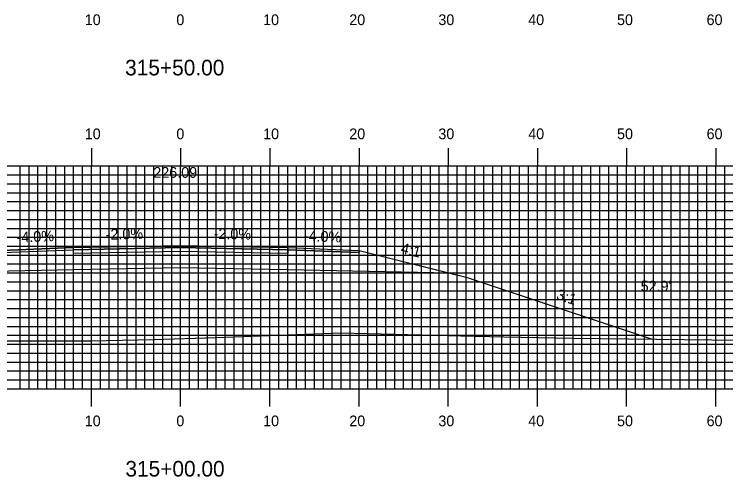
# Model space of a CAD drawing. Extents: x 1819244 to 1819587, y 442591 to 442811.
# Drawn here: x 1819391 to 1819470.8, y 442643.8 to 442695.7 of the extents above; entities that cross this region are included whole.
import ezdxf

# ---------------------------------------------------------------- set-up
doc = ezdxf.new("R2010")
doc.units = 0
for name, color, linetype in [('ANNOTATION', 7, 'Continuous'), ('D_Roadway_Centerline', 7, 'Continuous'), ('D_Roadway_Centerline_Text', 7, 'Continuous'), ('D_Roadway_Edge_Shoulder', 7, 'Continuous'), ('D_Roadway_Edge_TW', 7, 'Continuous'), ('D_Roadway_Pavement', 7, 'Continuous'), ('D_Roadway_SlopeLines', 7, 'Continuous'), ('D_Roadway_SubGrade', 7, 'Continuous'), ('D_Text_Standard', 7, 'Continuous'), ('H_V ANNOTATION', 7, 'Continuous'), ('MAJOR', 7, 'Continuous'), ('MINOR', 7, 'Continuous'), ('S_Roadway_Centerline', 7, 'Continuous')]:
    doc.layers.add(name, color=color, linetype=linetype)

msp = doc.modelspace()

# ---------------------------------------------------------------- linework, layer by layer
at = {"layer": 'D_Roadway_Centerline'}
msp.add_lwpolyline([(1819356.354, 442659.088), (1819377.665, 442666.192), (1819379.491, 442666.648), (1819389.665, 442669.192), (1819397.665, 442669.512), (1819409.665, 442669.752), (1819421.665, 442669.512), (1819429.665, 442669.192), (1819439.839, 442666.648), (1819441.665, 442666.192), (1819462.524, 442659.238)], dxfattribs=at)
at = {"layer": 'D_Roadway_Edge_Shoulder'}
for points in [[(1819397.665, 442669.512), (1819389.665, 442669.192), (1819389.665, 442668.942), (1819397.665, 442669.262)], [(1819421.665, 442669.512), (1819429.665, 442669.192), (1819429.665, 442668.942), (1819421.665, 442669.262)]]:
    msp.add_lwpolyline(points, close=True, dxfattribs=at)
at = {"layer": 'D_Roadway_Edge_TW'}
msp.add_lwpolyline([(1819397.665, 442669.262), (1819397.665, 442669.512), (1819409.665, 442669.752), (1819421.665, 442669.512), (1819421.665, 442669.262), (1819409.665, 442669.502)], close=True, dxfattribs=at)
at = {"layer": 'D_Roadway_Pavement'}
msp.add_lwpolyline([(1819397.665, 442668.845), (1819397.665, 442669.262), (1819409.665, 442669.502), (1819421.665, 442669.262), (1819421.665, 442668.845), (1819409.665, 442669.085)], close=True, dxfattribs=at)
at = {"layer": 'D_Roadway_SlopeLines'}
msp.add_lwpolyline([(1819429.665, 442669.192), (1819441.665, 442666.192), (1819462.524, 442659.238)], dxfattribs=at)
at = {"layer": 'D_Roadway_SubGrade'}
msp.add_lwpolyline([(1819397.665, 442667.012), (1819379.491, 442666.648), (1819389.665, 442669.192), (1819389.665, 442668.942), (1819397.665, 442669.262), (1819409.665, 442669.502), (1819421.665, 442669.262), (1819429.665, 442668.942), (1819429.665, 442669.192), (1819439.839, 442666.648), (1819421.665, 442667.012), (1819409.665, 442667.252)], close=True, dxfattribs=at)
at = {"layer": 'MAJOR'}
for p, q in [((1819399.665, 442680.669), (1819399.665, 442678.665)), ((1819409.665, 442680.669), (1819409.665, 442678.665)), ((1819419.665, 442680.669), (1819419.665, 442678.665)), ((1819429.665, 442680.669), (1819429.665, 442678.665)), ((1819439.665, 442680.669), (1819439.665, 442678.665)), ((1819449.665, 442680.669), (1819449.665, 442678.665)), ((1819459.665, 442680.669), (1819459.665, 442678.665)), ((1819469.665, 442680.669), (1819469.665, 442678.665)), ((1819269.665, 442678.665), (1819549.665, 442678.665)), ((1819269.665, 442678.665), (1819549.665, 442678.665)), ((1819399.665, 442653.665), (1819399.665, 442678.665)), ((1819409.665, 442653.665), (1819409.665, 442678.665)), ((1819419.665, 442653.665), (1819419.665, 442678.665)), ((1819429.665, 442653.665), (1819429.665, 442678.665)), ((1819439.665, 442653.665), (1819439.665, 442678.665)), ((1819449.665, 442653.665), (1819449.665, 442678.665)), ((1819459.665, 442653.665), (1819459.665, 442678.665)), ((1819469.665, 442653.665), (1819469.665, 442678.665)), ((1819269.665, 442673.665), (1819549.665, 442673.665)), ((1819269.665, 442668.665), (1819549.665, 442668.665)), ((1819269.665, 442663.665), (1819549.665, 442663.665)), ((1819269.665, 442658.665), (1819549.665, 442658.665)), ((1819269.665, 442653.665), (1819549.665, 442653.665)), ((1819269.665, 442653.665), (1819549.665, 442653.665)), ((1819399.665, 442651.661), (1819399.665, 442653.665)), ((1819409.665, 442651.661), (1819409.665, 442653.665)), ((1819419.665, 442651.661), (1819419.665, 442653.665)), ((1819429.665, 442651.661), (1819429.665, 442653.665)), ((1819439.665, 442651.661), (1819439.665, 442653.665)), ((1819449.665, 442651.661), (1819449.665, 442653.665)), ((1819459.665, 442651.661), (1819459.665, 442653.665)), ((1819469.665, 442651.661), (1819469.665, 442653.665))]:
    msp.add_line(p, q, dxfattribs=at)
at = {"layer": 'MINOR'}
for p, q in [((1819391.665, 442653.665), (1819391.665, 442678.665)), ((1819392.665, 442653.665), (1819392.665, 442678.665)), ((1819393.665, 442653.665), (1819393.665, 442678.665)), ((1819394.665, 442653.665), (1819394.665, 442678.665)), ((1819395.665, 442653.665), (1819395.665, 442678.665)), ((1819396.665, 442653.665), (1819396.665, 442678.665)), ((1819397.665, 442653.665), (1819397.665, 442678.665)), ((1819398.665, 442653.665), (1819398.665, 442678.665)), ((1819400.665, 442653.665), (1819400.665, 442678.665)), ((1819401.665, 442653.665), (1819401.665, 442678.665)), ((1819402.665, 442653.665), (1819402.665, 442678.665)), ((1819403.665, 442653.665), (1819403.665, 442678.665)), ((1819404.665, 442653.665), (1819404.665, 442678.665)), ((1819405.665, 442653.665), (1819405.665, 442678.665)), ((1819406.665, 442653.665), (1819406.665, 442678.665)), ((1819407.665, 442653.665), (1819407.665, 442678.665)), ((1819408.665, 442653.665), (1819408.665, 442678.665)), ((1819410.665, 442653.665), (1819410.665, 442678.665)), ((1819411.665, 442653.665), (1819411.665, 442678.665)), ((1819412.665, 442653.665), (1819412.665, 442678.665)), ((1819413.665, 442653.665), (1819413.665, 442678.665)), ((1819414.665, 442653.665), (1819414.665, 442678.665)), ((1819415.665, 442653.665), (1819415.665, 442678.665)), ((1819416.665, 442653.665), (1819416.665, 442678.665)), ((1819417.665, 442653.665), (1819417.665, 442678.665)), ((1819418.665, 442653.665), (1819418.665, 442678.665)), ((1819420.665, 442653.665), (1819420.665, 442678.665)), ((1819421.665, 442653.665), (1819421.665, 442678.665)), ((1819422.665, 442653.665), (1819422.665, 442678.665)), ((1819423.665, 442653.665), (1819423.665, 442678.665)), ((1819424.665, 442653.665), (1819424.665, 442678.665)), ((1819425.665, 442653.665), (1819425.665, 442678.665)), ((1819426.665, 442653.665), (1819426.665, 442678.665)), ((1819427.665, 442653.665), (1819427.665, 442678.665)), ((1819428.665, 442653.665), (1819428.665, 442678.665)), ((1819430.665, 442653.665), (1819430.665, 442678.665)), ((1819431.665, 442653.665), (1819431.665, 442678.665)), ((1819432.665, 442653.665), (1819432.665, 442678.665)), ((1819433.665, 442653.665), (1819433.665, 442678.665)), ((1819434.665, 442653.665), (1819434.665, 442678.665)), ((1819435.665, 442653.665), (1819435.665, 442678.665)), ((1819436.665, 442653.665), (1819436.665, 442678.665)), ((1819437.665, 442653.665), (1819437.665, 442678.665)), ((1819438.665, 442653.665), (1819438.665, 442678.665)), ((1819440.665, 442653.665), (1819440.665, 442678.665)), ((1819441.665, 442653.665), (1819441.665, 442678.665)), ((1819442.665, 442653.665), (1819442.665, 442678.665)), ((1819443.665, 442653.665), (1819443.665, 442678.665)), ((1819444.665, 442653.665), (1819444.665, 442678.665)), ((1819445.665, 442653.665), (1819445.665, 442678.665)), ((1819446.665, 442653.665), (1819446.665, 442678.665)), ((1819447.665, 442653.665), (1819447.665, 442678.665)), ((1819448.665, 442653.665), (1819448.665, 442678.665)), ((1819450.665, 442653.665), (1819450.665, 442678.665)), ((1819451.665, 442653.665), (1819451.665, 442678.665)), ((1819452.665, 442653.665), (1819452.665, 442678.665)), ((1819453.665, 442653.665), (1819453.665, 442678.665)), ((1819454.665, 442653.665), (1819454.665, 442678.665)), ((1819455.665, 442653.665), (1819455.665, 442678.665)), ((1819456.665, 442653.665), (1819456.665, 442678.665)), ((1819457.665, 442653.665), (1819457.665, 442678.665)), ((1819458.665, 442653.665), (1819458.665, 442678.665)), ((1819460.665, 442653.665), (1819460.665, 442678.665)), ((1819461.665, 442653.665), (1819461.665, 442678.665)), ((1819462.665, 442653.665), (1819462.665, 442678.665)), ((1819463.665, 442653.665), (1819463.665, 442678.665)), ((1819464.665, 442653.665), (1819464.665, 442678.665)), ((1819465.665, 442653.665), (1819465.665, 442678.665)), ((1819466.665, 442653.665), (1819466.665, 442678.665)), ((1819467.665, 442653.665), (1819467.665, 442678.665)), ((1819468.665, 442653.665), (1819468.665, 442678.665)), ((1819470.665, 442653.665), (1819470.665, 442678.665)), ((1819269.665, 442677.665), (1819549.665, 442677.665)), ((1819269.665, 442676.665), (1819549.665, 442676.665)), ((1819269.665, 442675.665), (1819549.665, 442675.665)), ((1819269.665, 442674.665), (1819549.665, 442674.665)), ((1819269.665, 442672.665), (1819549.665, 442672.665)), ((1819269.665, 442671.665), (1819549.665, 442671.665)), ((1819269.665, 442670.665), (1819549.665, 442670.665)), ((1819269.665, 442669.665), (1819549.665, 442669.665)), ((1819269.665, 442667.665), (1819549.665, 442667.665)), ((1819269.665, 442666.665), (1819549.665, 442666.665)), ((1819269.665, 442665.665), (1819549.665, 442665.665)), ((1819269.665, 442664.665), (1819549.665, 442664.665)), ((1819269.665, 442662.665), (1819549.665, 442662.665)), ((1819269.665, 442661.665), (1819549.665, 442661.665)), ((1819269.665, 442660.665), (1819549.665, 442660.665)), ((1819269.665, 442659.665), (1819549.665, 442659.665)), ((1819269.665, 442657.665), (1819549.665, 442657.665)), ((1819269.665, 442656.665), (1819549.665, 442656.665)), ((1819269.665, 442655.665), (1819549.665, 442655.665)), ((1819269.665, 442654.665), (1819549.665, 442654.665))]:
    msp.add_line(p, q, dxfattribs=at)
at = {"layer": 'S_Roadway_Centerline'}
msp.add_lwpolyline([(1819269.665, 442661.815), (1819272.843, 442661.651), (1819288.177, 442660.543), (1819298.828, 442660.207), (1819305.798, 442659.821), (1819309.315, 442659.838), (1819324.015, 442659.645), (1819335.7, 442659.474), (1819338.556, 442659.445), (1819349.95, 442659.119), (1819367.277, 442659.035), (1819373.268, 442659.053), (1819375.373, 442659.045), (1819379.124, 442659.023), (1819389.341, 442659.046), (1819399.588, 442659.041), (1819406.619, 442659.2), (1819413.605, 442659.425), (1819427.617, 442659.947), (1819441.069, 442659.597), (1819445.916, 442659.512), (1819453.663, 442659.344), (1819475.455, 442659.085)], dxfattribs=at)

# ---------------------------------------------------------------- texts
at = {"layer": 'ANNOTATION'}
for s, rotation, p in [('-4.0%', 2.29061, (1819391.296, 442670.059)), ('-2.0%', 1.14576, (1819401.271, 442670.384)), ('-2.0%', 358.85424, (1819413.351, 442670.478)), ('-4.0%', 357.70939, (1819423.456, 442670.242)), ('4:1', 345.96376, (1819434.257, 442668.905)), ('3:1', 341.56522, (1819451.698, 442663.755))]:
    msp.add_text(s, height=1.2, rotation=rotation, dxfattribs=at).set_placement(p)
at = {"layer": 'D_Roadway_Centerline'}
for s, p in [('C', (1819409.659, 442669.752)), ('L', (1819409.665, 442669.744))]:
    msp.add_text(s, height=0.0146, dxfattribs=at).set_placement(p)
at = {"layer": 'D_Roadway_Centerline_Text'}
msp.add_text('226.09', height=1.2, dxfattribs=at).set_placement((1819406.604, 442677.337))
at = {"layer": 'D_Text_Standard'}
msp.add_text("52.9'", height=1.2, dxfattribs=at).set_placement((1819461.25, 442664.586))
at = {"layer": 'H_V ANNOTATION'}
for s, height, p in [('10', 1.2, (1819398.915, 442694.465)), ('0', 1.2, (1819409.183, 442694.465)), ('10', 1.2, (1819418.915, 442694.465)), ('20', 1.2, (1819428.573, 442694.465)), ('30', 1.2, (1819438.562, 442694.465)), ('40', 1.2, (1819448.637, 442694.465)), ('50', 1.2, (1819458.594, 442694.465)), ('60', 1.2, (1819468.637, 442694.465)), ('315+50.00', 1.75, (1819403.438, 442688.821)), ('10', 1.2, (1819398.915, 442681.665)), ('0', 1.2, (1819409.183, 442681.665)), ('10', 1.2, (1819418.915, 442681.665)), ('20', 1.2, (1819428.573, 442681.665)), ('30', 1.2, (1819438.562, 442681.665)), ('40', 1.2, (1819448.637, 442681.665)), ('50', 1.2, (1819458.594, 442681.665)), ('60', 1.2, (1819468.637, 442681.665)), ('10', 1.2, (1819398.915, 442649.465)), ('0', 1.2, (1819409.183, 442649.465)), ('10', 1.2, (1819418.915, 442649.465)), ('20', 1.2, (1819428.573, 442649.465)), ('30', 1.2, (1819438.562, 442649.465)), ('40', 1.2, (1819448.637, 442649.465)), ('50', 1.2, (1819458.594, 442649.465)), ('60', 1.2, (1819468.637, 442649.465)), ('315+00.00', 1.75, (1819403.469, 442643.821))]:
    msp.add_text(s, height=height, dxfattribs=at).set_placement(p)

doc.saveas('drawing.dxf')
